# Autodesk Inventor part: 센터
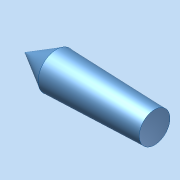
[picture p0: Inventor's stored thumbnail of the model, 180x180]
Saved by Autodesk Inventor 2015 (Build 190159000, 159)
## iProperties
Created: 2026-09
Part Number: 센터
Material: 일반
Document SubType Name: Modeling
Designer: SCD-A06
Density: 1 g/cm^3
Appearance: 기본값
Author: SCD-A06
Author: jhkim
Creation Date: 2026-08-27
Sending System: Autodesk Inventor 2027
Preprocessor: ST-DEVELOPER v20.1
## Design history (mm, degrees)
node "센터1"
node "솔리드1"
node "기준1"
